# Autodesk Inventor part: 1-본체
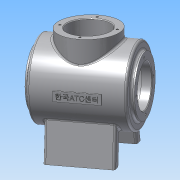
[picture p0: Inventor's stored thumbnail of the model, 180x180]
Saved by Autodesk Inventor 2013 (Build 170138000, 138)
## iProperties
Created: 2015-01
Part Number: 1-본체
Material: 알루미늄 6061
Document SubType Name: Modeling
Designer: Administrator
Density: 2.71 g/cm^3
Mass: 1021.7 g
Surface Area: 1061.52 cm^2
Volume: 377.013 cm^3
Author: Administrator
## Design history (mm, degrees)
sketch "스케치1"
  geometry: C1 r 50 at (0, 0); 1 further point
  constraints: 1 centre point, 1 coincident
  dimensions: "d0" = 100 diameter of C1
extrude "돌출1" new body sketch "스케치1" stored distance "d2" = 112; taper "d3" = 0 deg
sketch "스케치2"
  geometry: C1 r 38 at (0, 0); 1 further point
  constraints: 1 centre point, 1 coincident
  dimensions: "d4" = 76 diameter of C1
extrude "돌출2" join sketch "스케치2" distance "d6" = 5; taper "d7" = 0 deg
sketch "스케치3"
  geometry: C1 r 38 at (0, 0); 1 further point
  constraints: 1 centre point, 1 coincident
  dimensions: "d8" = 76 diameter of C1
extrude "돌출3" join sketch "스케치3" distance "d10" = 5; taper "d11" = 0 deg
node "작업 평면2"
sketch "스케치4"
  geometry: C1 r 38 at (0, 0); 1 further point
  constraints: 1 centre point, 1 coincident
  dimensions: "d13" = 76 diameter of C1
extrude "돌출4" join sketch "스케치4" stored distance "d15" = 5; taper "d16" = 0 deg
sketch "스케치6"
  geometry: L1 (20, 37.42)-(80, 48); L2 (80, 48)-(80, 34); L3 (80, 34)-(20, 23.42); L4 (20, 23.42)-(20, 37.42); L5 (0, 0)-(70, 0); L6 (80, -48)-(80, -34); L7 (80, -34)-(20, -23.42); L8 (20, -37.42)-(80, -48); L9 (20, -23.42)-(20, -37.42)
  constraints: 18 end point, 4 symmetric about line, 2 parallel, 1 perpendicular, 1 vertical
  dimensions: "d27" = 14 distance of L1.end L2.end; "d29" = 100 deg angle of L2 L1; "d31" = 96 diameter of L1.end L5; "d32" = 60 distance between parallel lines of L4 L2; "d33" = 80 distance from line of L5.start L2; "d34" = 10 distance from line of L5.end L2
extrude "돌출5" join sketch "스케치6" stored distance "d35" = 80; taper "d36" = 0 deg
sketch "스케치7"
  geometry: L1 (38, 61)-(-38, 61) reference; L2 (-38, -61)-(38, -61) reference; L3 (0, 61)-(0, -61); L4 (27, 61)-(27, 48); L5 (27, 48)-(45, 48); L6 (45, 48)-(45, -49); L7 (45, -49)-(27, -49); L8 (27, -49)-(27, -61); L9 (27, 61)-(0, 61); L10 (27, -61)-(0, -61); L11 (50, 56)-(-50, 56) reference; L12 (-50, -56)-(50, -56) reference; 1 further point
  constraints: 16 end point, 3 collinear, 3 parallel, 2 midpoint, 2 perpendicular, 2 point on line
  dimensions: "d38" = 90 diameter of L6 L3; "d40" = 54 diameter of L4 L3; "d99" = 8 distance between parallel lines of L5 L11; "d100" = 7 distance between parallel lines of L12 L7
revolve "회전1" sketch "스케치7" stored, may be unused: angle "d43" = 90 deg
hole "구멍1" diameter "d46" = 54; stored, may be unused: countersink angle "d50" = 90 deg, drill point angle "d52" = 0 deg; dims "d44" = 10, "d45" = 10, "d47" = 6, "d48" = 4, "d49" = 2, "d51" = 8
sketch "스케치8"
  geometry: 2 further points
  constraints: 1 horizontal alignment
  dimensions: "d53" = 32 distance of point (0, 0) point (-32, 0)
hole "구멍2" sketch "스케치8" at (-32, 0) diameter "d54" = 3.242; stored, may be unused: countersink angle "d58" = 90 deg, drill point angle "d60" = 118 deg; dims "d55" = 8, "d56" = 4, "d57" = 2, "d59" = 10
sketch "스케치9"
  geometry: 2 further points
  constraints: 1 horizontal alignment
  dimensions: "d64" = 32 distance of point (0, 0) point (-32, 0)
hole "구멍3" sketch "스케치9" at (-32, 0) diameter "d65" = 3.242; stored, may be unused: countersink angle "d69" = 90 deg, drill point angle "d71" = 118 deg; dims "d66" = 8, "d67" = 4, "d68" = 2, "d70" = 10
sketch "스케치10"
  geometry: 2 further points
  dimensions: "d75" = 32 distance of point (0, 0) point (32, 0)
hole "구멍4" sketch "스케치10" at (32, 0) diameter "d76" = 3.242; stored, may be unused: countersink angle "d80" = 90 deg, drill point angle "d82" = 118 deg; dims "d77" = 8, "d78" = 4, "d79" = 2, "d81" = 10
node "작업 평면4"
sketch "스케치12"
  geometry: L1 (-6, 26)-(6, 26); L2 (6, 26)-(6, -28); L3 (6, -28)-(-6, -28); L4 (-6, -28)-(-6, 26); L5 (38, 61)-(-38, 61) reference; 3 further points
  constraints: 8 end point, 3 midpoint, 2 parallel, 1 horizontal, 1 perpendicular, 1 vertical alignment
  dimensions: "d87" = 12 distance of L1.start L1.end; "d89" = 54 distance of L1.end L2.end; "d101" = 62 distance from line of point (6, -1) L5
extrude "돌출6" join sketch "스케치12" stored distance "d90" = 80; taper "d91" = 0 deg
sketch "스케치13"
  geometry: L1 (38, 61)-(-38, 61) reference; 2 further points
  constraints: 1 midpoint, 1 vertical alignment, 1 other
  dimensions: "d102" = 62 distance from line of point (0, -1) L1
feature "엠보싱1" sketch "스케치13" dims "d92" = 0.5, "d93" = 0
fillet "모깎기1" dims "d94" = 3
fillet "모깎기2" dims "d95" = 3
chamfer "모따기1" distance "d96" = 1; stored, may be unused: second distance "d97" = 2, angle "d98" = 45 deg
node "솔리드1"
pattern_circular "원형 패턴1" dims angle "d62" = 360 deg
pattern_circular "원형 패턴2" dims angle "d73" = 360 deg
pattern_circular "원형 패턴3" dims angle "d84" = 360 deg
other parameters: "d12" = -62, "d86" = 52
